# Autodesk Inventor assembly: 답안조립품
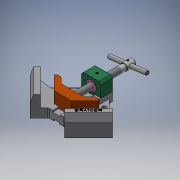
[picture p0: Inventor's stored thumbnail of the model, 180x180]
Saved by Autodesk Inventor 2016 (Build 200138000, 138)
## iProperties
Created: 2020-05
Part Number: 답안조립품
Document SubType Name: Assembly
Designer: MIRAE
Author: MIRAE
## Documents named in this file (11)
- C:\Users\MIRAE\Desktop\700506V1007\답안조립품.iam
- C:\Users\MIRAE\Desktop\700506V1007\베이스.ipt
- C:\Users\MIRAE\Desktop\700506V1007\리드스크류.ipt
- C:\Users\MIRAE\Desktop\700506V1007\서포트.ipt
- C:\Users\MIRAE\Desktop\700506V1007\부시.ipt
- C:\Users\MIRAE\Desktop\700506V1007\멈춤나사 M4x10.ipt
- C:\Users\MIRAE\Desktop\700506V1007\핸들.ipt
- C:\Users\MIRAE\Desktop\700506V1007\멈춤나사 M4x5.ipt
- C:\Users\MIRAE\Desktop\700506V1007\조.ipt
- C:\Users\MIRAE\Desktop\700506V1007\평행 핀 2.5x24.ipt
- C:\Users\MIRAE\Desktop\700506V1007\볼트 M4x16.ipt
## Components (1 placed, 1 different names)
1. 핸들:2 — 강체:2
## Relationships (1: WeldJoint 1)
- 강체:2 [WeldJoint]: 핸들:2
